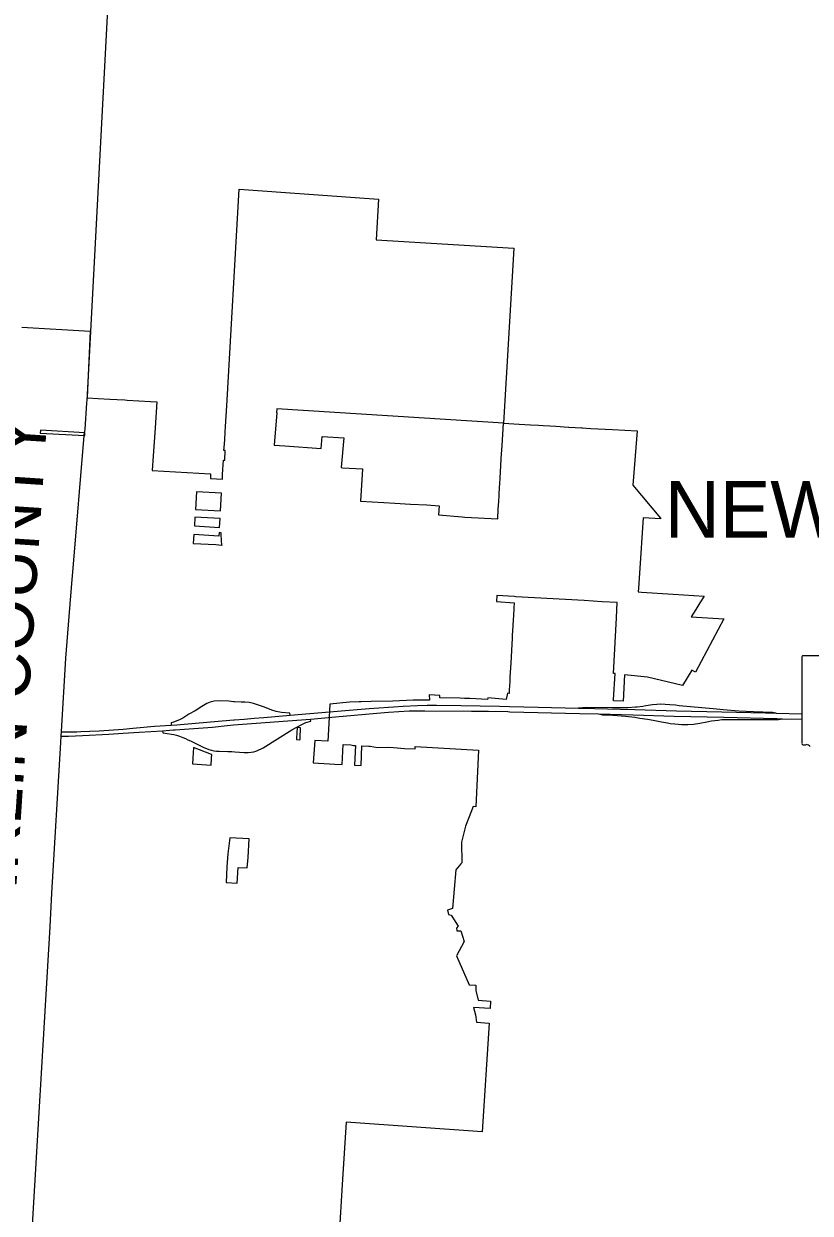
# Model space of a CAD drawing. Extents: x 1853412 to 2125412, y 679418 to 855418.
# Drawn here: x 1893459 to 1908987, y 748060 to 771538 of the extents above; entities that cross this region are included whole.
import ezdxf

# ---------------------------------------------------------------- set-up
doc = ezdxf.new("R2010")
doc.units = 0
for name, color, linetype in [('GM_X_Corporation', 7, 'Continuous'), ('GM_X_Corporation_Text', 7, 'Continuous'), ('GM_X_County', 7, 'Continuous'), ('GM_X_County_Text', 7, 'Continuous'), ('GM_X_State_Location', 7, 'Continuous'), ('GM_X_State_Shield', 7, 'Continuous'), ('UT_P_Electric', 7, 'Continuous')]:
    doc.layers.add(name, color=color, linetype=linetype)

msp = doc.modelspace()

# ---------------------------------------------------------------- linework, layer by layer
at = {"layer": 'GM_X_Corporation'}
msp.add_lwpolyline([(1893418, 765551), (1894769, 765471), (1894712, 764159), (1894712, 764155), (1894931, 764143), (1895155, 764131), (1895304, 764122), (1895453, 764114), (1895503, 764111), (1895961, 764085), (1896084, 764079), (1896051, 763565), (1896009, 762914), (1896003, 762820), (1895997, 762719), (1897148, 762656), (1897144, 762560), (1897381, 762550), (1897386, 762642), (1897392, 762737), (1897397, 762830), (1897404, 762926), (1897426, 762925), (1897437, 763113), (1897411, 763115), (1897418, 763174), (1897427, 763329), (1897437, 763486), (1897443, 763587), (1897468, 764000), (1897714, 768272), (1900466, 768079), (1900419, 767275), (1903136, 767111), (1902928, 763655), (1898458, 763938), (1898451, 763857), (1898456, 763857), (1898400, 763221), (1898614, 763205), (1899330, 763156), (1899348, 763389), (1899779, 763364), (1899729, 762777), (1899750, 762776), (1900145, 762752), (1900106, 762115), (1900565, 762088), (1900785, 762076), (1901097, 762058), (1901418, 762040), (1901659, 762026), (1901646, 761844), (1902112, 761807), (1902165, 761801), (1902816, 761764), (1902827, 761960), (1902836, 762109), (1902843, 762224), (1902845, 762257), (1902858, 762475), (1902863, 762554), (1902872, 762710), (1902877, 762804), (1902887, 762959), (1902902, 763214), (1902928, 763655), (1903239, 763637), (1903465, 763624), (1903620, 763615), (1903713, 763609), (1903844, 763601), (1903962, 763594), (1904217, 763578), (1904223, 763578), (1904348, 763571), (1904487, 763561), (1904478, 763563), (1904653, 763552), (1905082, 763527), (1905567, 763503), (1905486, 762432), (1906030, 761779), (1906029, 761768), (1905686, 761789), (1905615, 760693), (1905596, 760400), (1905591, 760324), (1905656, 760317), (1906280, 760277), (1906894, 760237), (1906810, 760108), (1906727, 759978), (1906634, 759833), (1907282, 759791), (1906721, 758740), (1906649, 758777), (1906466, 758475), (1905775, 758639), (1905323, 758690), (1905293, 758169), (1905103, 758174), (1905105, 758193), (1905105, 758199), (1905136, 758711), (1905105, 758714), (1905162, 759814), (1905177, 760113), (1904880, 760131), (1904521, 760151), (1903173, 760229), (1903148, 760230), (1902799, 760251), (1902791, 760132), (1903141, 760107), (1903135, 760006), (1903126, 759848), (1903123, 759781), (1903115, 759654), (1903105, 759464), (1903101, 759409), (1903088, 759168), (1903073, 758915), (1903058, 758650), (1903053, 758560), (1903048, 758472), (1903044, 758393), (1903040, 758321), (1903009, 758323), (1902983, 758197), (1902619, 758231), (1902616, 758197), (1902265, 758217), (1902161, 758223), (1902076, 758226), (1901672, 758236), (1901675, 758281), (1901466, 758294), (1901468, 758184), (1901150, 758184), (1900745, 758167), (1900320, 758158), (1900122, 758153), (1900082, 758152), (1899892, 758148), (1899499, 758110), (1899479, 757726), (1899460, 757376), (1899207, 757391), (1899176, 756947), (1899599, 756924), (1899748, 756916), (1899767, 757312), (1899918, 757303), (1899971, 757289), (1900008, 757291), (1899987, 756902), (1900120, 756895), (1900136, 757284), (1900270, 757277), (1900297, 757276), (1900441, 757255), (1900670, 757259), (1900760, 757255), (1900975, 757234), (1901185, 757226), (1901188, 757275), (1902435, 757202), (1902383, 756081), (1902330, 756085), (1902298, 756003), (1902179, 755701), (1902099, 755385), (1902110, 754973), (1902110, 754973), (1902091, 754953), (1901989, 754839), (1901921, 754076), (1901825, 754044), (1901844, 753954), (1901897, 753943), (1902038, 753726), (1902002, 753689), (1902008, 753632), (1902088, 753632), (1902154, 753423), (1902001, 753142), (1902253, 752565), (1902382, 752561), (1902386, 752456), (1902429, 752263), (1902675, 752246), (1902666, 752099), (1902341, 752122), (1902376, 751973), (1902400, 751828), (1902647, 751812), (1902512, 749668), (1899822, 749855), (1899752, 748730), (1899677, 747536)], dxfattribs=at)
for points in [[(1893785, 763459), (1893785, 763459), (1894662, 763410), (1894665, 763467), (1893788, 763517)], [(1896853, 761950), (1897343, 761922), (1897364, 762271), (1896871, 762299)], [(1896827, 761626), (1897323, 761598), (1897334, 761770), (1896838, 761800)], [(1897357, 761492), (1897317, 761494), (1897313, 761424), (1896816, 761454), (1896806, 761280), (1897248, 761257), (1897367, 761247), (1897368, 761238), (1897357, 761450)], [(1898846, 757409), (1898912, 757406), (1898913, 757415), (1898914, 757436), (1898914, 757436), (1898926, 757642), (1898860, 757646), (1898847, 757438)], [(1896789, 756930), (1897159, 756904), (1897168, 757039), (1897172, 757114), (1897167, 757114), (1896807, 757252), (1896794, 757039)], [(1897458, 754590), (1897672, 754574), (1897691, 754886), (1897872, 754876), (1897889, 755084), (1897909, 755448), (1897530, 755472), (1897488, 755152), (1897469, 754900)]]:
    msp.add_lwpolyline(points, close=True, dxfattribs=at)
at = {"layer": 'GM_X_County'}
msp.add_lwpolyline([(1893594, 747156), (1893977, 753711), (1894016, 754374), (1894190, 757348), (1894196, 757481), (1894202, 757566), (1894292, 759017), (1894358, 759840), (1894417, 760570), (1894435, 760790), (1894651, 763412), (1894656, 763471), (1894662, 763482), (1894666, 763499), (1894670, 763535), (1894701, 764047), (1894703, 764067), (1894709, 764094), (1895160, 772568)], dxfattribs=at)
at = {"layer": 'GM_X_State_Shield'}
for p, q in [((1908820, 759036), (1908820, 757335)), ((1909668, 759065), (1908848, 759065))]:
    msp.add_line(p, q, dxfattribs=at)
for centre, major_axis, start_param, end_param in [((1908852, 759039), (32.5, 0), 1.712693, 3.28349), ((1908853, 757331), (32.7, 0), 3.00124, 4.508301), ((1908857, 757505), (250, 0), 4.665946, 4.897461), ((1908909, 757237), (90.1, 0), 0.519207, 1.627899)]:
    msp.add_ellipse(centre, major_axis=major_axis, ratio=0.8, start_param=start_param, end_param=end_param, dxfattribs=at)
at = {"layer": 'UT_P_Electric'}
msp.add_line((1896201, 757584), (1896413, 757598), dxfattribs=at)
for points in [[(1897603, 758157), (1897556, 758161), (1897505, 758165), (1897339, 758174), (1897215, 758165), (1897142, 758150), (1897073, 758123), (1896972, 758061), (1896843, 757979), (1896717, 757908), (1896600, 757833), (1896531, 757797), (1896413, 757750), (1896367, 757741), (1896368, 757693)], [(1898212, 758051), (1897994, 758122), (1897912, 758141), (1897826, 758148), (1897749, 758150), (1897621, 758156), (1897603, 758157)], [(1898717, 757888), (1898712, 757933), (1898550, 757944), (1898440, 757962), (1898356, 757991), (1898212, 758051)], [(1898717, 757888), (1899572, 757961), (1899804, 757981), (1900281, 758022), (1900662, 758051), (1900756, 758057), (1900947, 758068), (1901231, 758081), (1901421, 758085), (1901610, 758086), (1902087, 758079), (1902853, 758066), (1903049, 758061)], [(1899542, 757850), (1900277, 757914), (1900661, 757948), (1901068, 757974), (1901379, 757974), (1902301, 757970), (1902635, 757969), (1903018, 757960), (1903055, 757959)], [(1903049, 758061), (1903615, 758049), (1904409, 758029), (1904476, 758027), (1905239, 758009), (1905527, 758001), (1906349, 757978), (1907245, 757958), (1908102, 757935), (1908313, 757929), (1908820, 757916)], [(1903055, 757959), (1904434, 757923), (1904805, 757914), (1905489, 757897), (1906299, 757873), (1907280, 757850), (1908328, 757822), (1908439, 757819), (1908820, 757810)], [(1906401, 758078), (1906328, 758087), (1906214, 758098), (1906126, 758103), (1906030, 758106), (1905957, 758100), (1905870, 758092), (1905739, 758075), (1905680, 758065), (1905573, 758050), (1905534, 758047), (1905388, 758037), (1905086, 758037), (1904574, 758040), (1904409, 758029)], [(1904805, 757914), (1904887, 757897), (1905087, 757889), (1905338, 757869), (1905526, 757850), (1905625, 757834), (1905776, 757812), (1905887, 757790), (1906050, 757761), (1906169, 757738), (1906222, 757724)], [(1908313, 757929), (1908243, 757945), (1907870, 757954), (1907578, 757969), (1907268, 757996), (1907072, 758018), (1906401, 758078)], [(1894203, 757563), (1894231, 757563), (1894336, 757563), (1894405, 757564), (1894505, 757562), (1894587, 757567), (1894764, 757573), (1894949, 757582), (1895043, 757587), (1895137, 757593), (1895232, 757601), (1895328, 757608), (1895422, 757617), (1895612, 757633), (1896043, 757672), (1896368, 757693)], [(1896368, 757693), (1896480, 757702), (1897144, 757760), (1897607, 757799), (1897621, 757800), (1897811, 757814), (1898008, 757829), (1898196, 757846), (1898717, 757888)], [(1896413, 757598), (1896450, 757600), (1897186, 757657), (1897474, 757687)], [(1897474, 757687), (1897600, 757700), (1899122, 757813), (1899542, 757850)], [(1897565, 757171), (1897629, 757167), (1897812, 757153), (1897887, 757153), (1897951, 757159), (1898001, 757166), (1898062, 757187), (1898183, 757247), (1898754, 757600), (1898933, 757702), (1899028, 757747), (1899124, 757773), (1899122, 757813)], [(1906222, 757724), (1906311, 757719), (1906445, 757704), (1906572, 757705), (1906683, 757715), (1906810, 757736), (1906943, 757761), (1907040, 757777), (1907171, 757794), (1907245, 757802), (1907441, 757806), (1907658, 757806), (1908362, 757805), (1908439, 757819)], [(1894197, 757479), (1894345, 757473), (1894618, 757489), (1895137, 757519), (1895423, 757535), (1895739, 757554), (1896201, 757584)], [(1896201, 757584), (1896203, 757541), (1896373, 757519), (1896422, 757508), (1896476, 757494), (1896534, 757478), (1896598, 757450), (1896651, 757429), (1896697, 757407), (1896750, 757381), (1896803, 757355), (1896856, 757329), (1896909, 757304), (1896962, 757279), (1897014, 757255), (1897064, 757233), (1897114, 757214), (1897164, 757199), (1897214, 757188), (1897264, 757182), (1897314, 757179), (1897489, 757174), (1897565, 757171)]]:
    msp.add_lwpolyline(points, dxfattribs=at)

# ---------------------------------------------------------------- texts
at = {"layer": 'GM_X_Corporation_Text'}
msp.add_text('NEW ALBANY', height=1120, rotation=0, dxfattribs=at).set_placement((1906118, 761394))
at = {"layer": 'GM_X_County_Text'}
msp.add_text('FRANKLIN COUNTY', height=1000, rotation=86.2274, dxfattribs=at).set_placement((1893094, 751191))
at = {"layer": 'GM_X_State_Location'}
msp.add_text('161', height=1, rotation=0, dxfattribs=at).set_placement((1908751, 757662))

doc.saveas('drawing.dxf')
